// Mitsubishi GX Works2 project: 17.计数程序   PLC: FX3U/FX3UC

PROGRAM MAIN
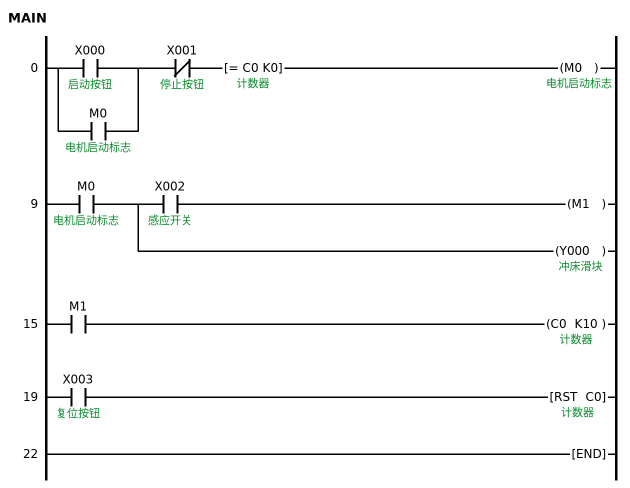
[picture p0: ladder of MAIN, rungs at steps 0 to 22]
0     LD      X000  ; 启动按钮
      OR      M0  ; 电机启动标志
      ANI     X001  ; 停止按钮
      AND=    C0 K0  ; 计数器
      OUT     M0  ; 电机启动标志
        [note] 比较指令：C未到10时必须复位启动
9     LD      M0  ; 电机启动标志
      MPS
      AND     X002  ; 感应开关
      OUT     M1
      MPP
      OUT     Y000  ; 冲床滑块
15    LD      M1
      OUT     C0 K10  ; 计数器
19    LD      X003  ; 复位按钮
      RST     C0  ; 计数器
        [note] 计数器必须用RST重置
22    END
END_PROGRAM
